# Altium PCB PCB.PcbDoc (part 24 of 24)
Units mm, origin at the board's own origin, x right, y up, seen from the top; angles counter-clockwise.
Board outline 100 x 160 mm, 10 copper layers (TOP_L1, L2, L3, L4, L5, L6, L7, L8, L9, BOTTOM_L10), stack 1.946 mm thick; 1358 components, 1149 nets, 6777 pads, 10914 vias.
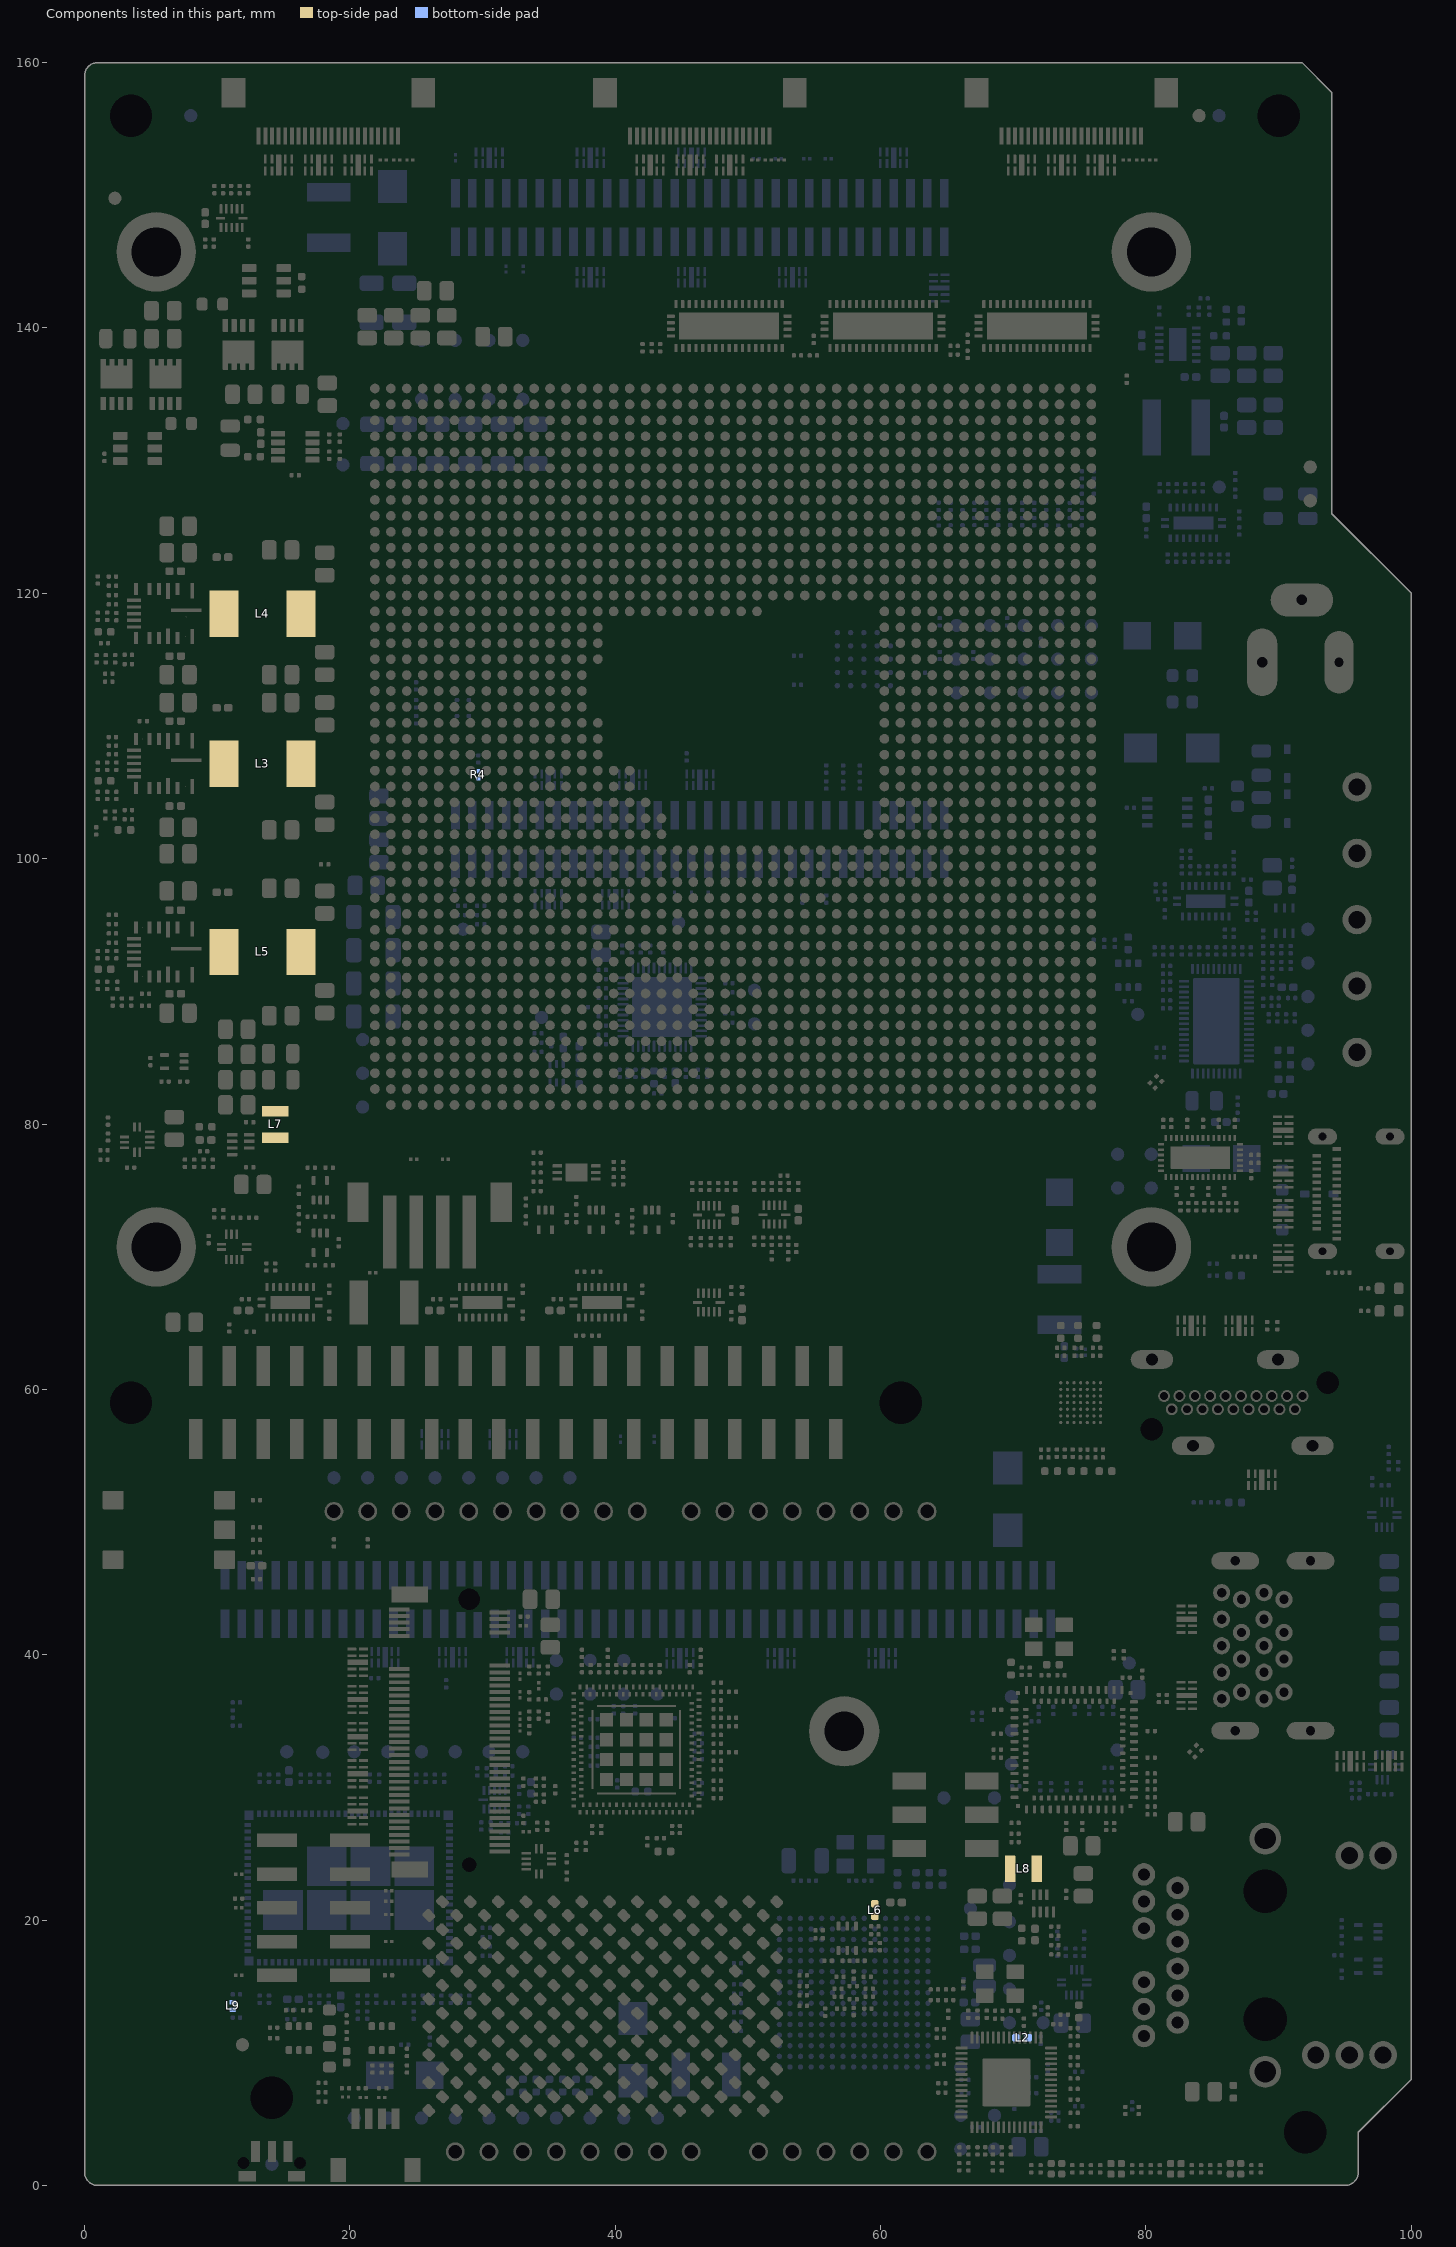
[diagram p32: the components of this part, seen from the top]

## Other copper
TOP_L1:
  pour cut-out: 81.4,79.1 78.2,82.3 69.2,82.3 69.2,80.6 69.8,80 70.338,80 71.838,78.5 77.3,78.5 78.3,77.5 81.4,77.5
  region net +5V: 19.369,89.511 19.369,96.421 14.48,96.421 14.48,98.496 13.37,98.496 13.37,87.431 14.48,87.431 14.48,89.511 17.84,89.511
  region net +5V: 10.14,70.178 10.14,69.008 8.755,69.008 8.755,70.178
  region net PA_VBUS: 2.333,137.7 2.333,140.319 3.899,140.319 3.899,141.893 3.221,142.572 0.808,142.572 0.808,135.438 3.595,135.438 3.595,137.7
  region net NetQ1_S: 11.066,139.698 12.973,139.698 13.104,139.829 13.104,140.672 13.347,140.914 14.766,140.914 14.766,139.698 16.495,139.698 16.495,141.822 11.066,141.822 11.066,140.463
  region net NetQ5_S: 6.635,134.802 4.619,134.802 4.446,134.629 4.446,133.922 4.111,133.586 2.935,133.586 2.935,134.802 1.206,134.802 1.206,132.571 5.67,132.571 5.837,132.571 5.837,133.689 6.635,133.689 6.635,134.037
  region net +3V3: 77.543,26.336 77.543,22.6 73.3,22.6 72.435,22.6 72.435,24.582 75.3,24.582 75.3,26.336
  region net +3V3: 30.7,133.865 26.2,133.865 26.2,136.034 24.85,136.034 24.85,138.365 30.7,138.365
  region net +3V3: 20.55,139.8 20.55,136.95 30.7,136.95 30.7,139.8
  region net +3V3: 19.369,115.01 19.369,121.92 14.48,121.92 14.48,123.795 13.37,123.795 13.37,111.765 14.48,111.765 14.48,115.01 17.84,115.01
  region net +3V3: 19.369,103.71 19.369,110.62 14.48,110.62 14.48,112.495 13.37,112.495 13.37,101.43 14.48,101.43 14.48,103.71 17.84,103.71
  region net +3V3: 23.625,99.036 23.625,103.014 23.075,103.565 21.12,103.565 21.12,110.62 19.1,110.62 19.1,100.765 19.1,99.036
  region net +3V3: 2.982,80.569 5.4,80.569 5.4,82.341 2.982,82.341
  region net +3V3: 34.142,23.118 34.142,22.915 34.541,22.915 34.541,22.423 33.77,22.423 33.612,22.581 33.026,22.581 33.026,23.395 33.789,23.395 33.789,23.118
  pour cut-out: 90.8,88.4 90.8,84 88.5,81.7 85,81.7 78.3,88.4 78.3,100.9 78.9,101.7 78.9,117.3 77.2,119 77.2,127 79.1,128.9 81.8,128.9 83.2,130.3 87,130.3 88.2,129.1 88.2,123.8 85.7,121.3 85.7,90.9 88.1,88.5
  region net PA_VBUS: 95.135,73.354 97.635,73.354 97.635,76.063 95.135,76.063
  region net 7V-24V: 16.9,139.063 16.9,143.358 19.5,143.358 19.5,136.828 14.106,136.828 14.106,139.063 14.405,139.063
  pour cut-out: 86.754,80.471 86.754,83.746 82.5,88 81.6,88 78,91.6 74.98,91.6 74.98,81.6 78.65,81.6 80.85,79.4 86.8,79.4
  region net SOM_VREG_MDPX3_1P8: 76.978,130.488 78.615,130.488 78.615,129.787 77.672,128.844 76.978,128.844
  pour cut-out: 0,46 0,0 10.2,0 10.2,38.781 8.392,40.589 8.392,46
  region net NetC76_1: 2.455,88.188 6.723,88.214 6.723,86.514 2.455,86.514
  region net NetC256_2: 11.709,133.401 11.709,135.699 12.795,136.785 12.795,139.063 8.2,139.063 8.2,137.7 4.906,137.7 4.906,135.438 7.696,135.438 8.4,134.734 8.4,133.8 8.941,133.259 10.089,133.259 10.239,133.109 10.239,132.431 11.709,132.431
  region net NetC96_2: 7.594,93.341 8.837,93.341 9.4,93.904 9.4,94.716 11.6,94.716 11.6,91.216 9.4,91.216 9.4,92.066 8.875,92.591 7.809,92.591
  region net NetC86_2: 7.594,118.84 8.837,118.84 9.4,119.403 9.4,120.215 11.6,120.215 11.6,116.715 9.4,116.715 9.4,117.565 8.875,118.09 7.809,118.09
  region net NetC75_2: 7.594,107.54 8.837,107.54 9.4,108.103 9.4,108.915 11.6,108.915 11.6,105.415 9.4,105.415 9.4,106.265 8.875,106.79 7.809,106.79
  region net GND: 77.341,35.599 71.841,35.599 71.841,30.099 76.941,30.099 77.341,30.499
  region net GND: 7.475,120.765 7.775,120.765 7.775,120.265 8.25,120.265 8.25,120.065 8.8,120.065 8.8,119.565 7.475,119.565
  region net GND: 7.475,116.165 7.775,116.165 7.775,116.665 8.25,116.665 8.25,116.865 8.8,116.865 8.8,117.365 7.475,117.365
  region net GND: 7.475,109.465 7.775,109.465 7.775,108.965 8.25,108.965 8.25,108.765 8.8,108.765 8.8,108.265 7.475,108.265
  region net GND: 7.475,104.865 7.775,104.865 7.775,105.365 8.25,105.365 8.25,105.565 8.8,105.565 8.8,106.065 7.475,106.065
  region net GND: 7.475,95.266 7.775,95.266 7.775,94.766 8.25,94.766 8.25,94.566 8.8,94.566 8.8,94.066 7.475,94.066
  region net GND: 7.475,90.666 7.775,90.666 7.775,91.166 8.25,91.166 8.25,91.366 8.8,91.366 8.8,91.866 7.475,91.866
  region net "1V05_PG (PULLUP 1V8)_1": 72.906,22.309 72.906,21.409 73.032,21.409 73.156,21.533 73.156,22.309
  region net NetR337_2: 2.665,79.319 3.365,79.319 3.365,79.423 3.269,79.519 2.665,79.519
  region net NetR217_2: 3.2,91.166 4.25,91.166 4.25,90.666 4.525,90.666 4.525,91.394 4.353,91.566 3.2,91.566
  region net NetC114_2: 3.2,94.766 4.25,94.766 4.25,95.266 4.525,95.266 4.525,94.366 3.2,94.366
  region net NetC96_2: 8.8,92.591 8.8,92.841 8.3,92.841 8.3,93.341 6.5,93.341 6.5,92.841 6.5,92.591
  region net NetC144_2: 3.2,108.965 4.25,108.965 4.25,109.465 4.525,109.465 4.525,108.565 3.2,108.565
  region net "3V3_PG (PULLUP 3V3)_1": 3.2,105.365 4.25,105.365 4.25,104.865 4.525,104.865 4.525,105.593 4.353,105.765 3.2,105.765
  region net NetC75_2: 8.8,106.79 8.8,107.04 8.3,107.04 8.3,107.54 6.5,107.54 6.5,107.04 6.5,106.79
  region net NetR123_2: 3.2,116.665 4.25,116.665 4.25,116.165 4.525,116.165 4.525,116.893 4.353,117.065 3.2,117.065
  region net NetC145_2: 3.2,120.265 4.25,120.265 4.25,120.765 4.525,120.765 4.525,119.865 3.2,119.865
  region net NetC86_2: 8.8,118.09 8.8,118.34 8.3,118.34 8.3,118.84 6.5,118.84 6.5,118.34 6.5,118.09
  region net NetR150_2: 12.818,77.816 11.918,77.816 11.918,77.69 12.042,77.566 12.818,77.566
  region net MD_GPIO_51_1: 35.541,23.924 34.841,23.924 34.841,23.82 34.937,23.724 35.541,23.724
  region net NetR336_2: 11.768,72.036 11.768,71.336 11.872,71.336 11.968,71.432 11.968,72.036
L5:
  pour cut-out: 0,46 0,0 10.2,0 10.2,38.781 8.392,40.589 8.392,46
L6:
  pour cut-out: 0,46 0,0 10.2,0 10.2,38.781 8.392,40.589 8.392,46
L2:
  pour cut-out: 0,46 0,0 10.2,0 10.2,38.781 8.392,40.589 8.392,46
L3:
  pour cut-out: 0,46 0,0 10.2,0 10.2,38.781 8.392,40.589 8.392,46
L4:
  pour cut-out: 0,46 0,0 10.2,0 10.2,38.781 8.392,40.589 8.392,46
L7:
  pour cut-out: 0,46 0,0 10.2,0 10.2,38.781 8.392,40.589 8.392,46
L8:
  pour cut-out: 0,46 0,0 10.2,0 10.2,38.781 8.392,40.589 8.392,46
L9:
  pour cut-out: 0,46 0,0 10.2,0 10.2,38.781 8.392,40.589 8.392,46
BOTTOM_L10:
  rectangle net NetC84_2: 84.675,82.701 85.953,83.246
  region net GND: 8,1.651 8,0.651 0.5,0.651 0.5,20.901 10.5,20.901 10.5,19.901 1.5,19.901 1.5,13.151 6.75,13.151 6.75,16.151 5.25,16.151 5.25,17.151 8.75,17.151 8.75,13.151 10.01,13.151 10.01,12.151 5.75,12.151 5.75,6.151 2.5,6.151 2.5,7.151 4,7.151 4,12.151 1.5,12.151 1.5,1.651
  region net +3V3: 21.15,110.7 17.943,110.7 14.85,110.7 14.85,103.2 19.35,103.2 19.35,99 21.15,99
  region net NetLOVE_X: 1461 vertices and 0 holes, not listed, extent 68.468,21.376 70.924,23.748
  region net ANT1_PI_29: 4,39.651 4,35.901 10.01,35.901 10.01,36.901 5,36.901 5,39.651
  pour cut-out: 10.136,12.698 10.136,12.605 11.167,12.605 11.167,12.698
  region net ANT0_PI_29: 10.01,13.151 10.463,12.698 11.201,12.698 11.201,12.605 10.464,12.605 10.01,12.151
  region net ANT1_PI_29: 10.01,36.901 10.463,36.448 11.201,36.448 11.201,36.355 10.464,36.355 10.01,35.901
  pour cut-out: 0,46 0,0 10.2,0 10.2,38.781 8.392,40.589 8.392,46
  region net PA_VBUS: 97.603,73.325 95.024,73.325 95.024,76.181 97.603,76.181
  pour cut-out: 10.153,36.571 10.153,36.234 11.185,36.234 11.185,36.571
  region net DVDD18: 73.815,13.833 73.815,13.454 75.985,13.454 75.985,13.833
  region net GND: 80.803,102.652 80.803,104.753 82.403,104.753 82.403,102.253 81.202,102.253
  region net GND: 91.133,95.674 91.133,94.973 89.733,94.973 89.733,95.516 89.89,95.674
  region net GND: 16.45,25.56 16.45,22.56 13.45,22.56 13.45,25.06 13.95,25.56
  region net NetR154_2: 97.471,51.846 97.471,51.146 97.367,51.146 97.271,51.242 97.271,51.846
  region net NetR182_2: 98.515,30.235 98.515,30.935 98.619,30.935 98.715,30.838 98.715,30.235
  region net NetC36_2: 74.081,16.609 74.081,15.909 73.977,15.909 73.881,16.005 73.881,16.609
  text ".Version" at 87.016,3.5 h1

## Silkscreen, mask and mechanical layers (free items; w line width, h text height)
Board:
  the board outline again, w0.2
TH_CLEARANCES:
  circle w0.05: c97.727,79.628 r3
  circle w0.05: c95.9,105.4 r3
  circle w0.05: c95.9,100.4 r3
  circle w0.05: c95.9,95.4 r3
  circle w0.05: c95.9,90.4 r3
  circle w0.05: c95.9,85.4 r3
  circle w0.05: c92.361,79.474 r3
  circle w0.05: c78.857,62.364 r3
  circle w0.05: c85.054,47.465 r3
  circle w0.05: c95.334,9.83 r3.711
  circle w0.05: c92.794,9.83 r3.711
  circle w0.05: c88.984,8.56 r3.711
  circle w0.05: c94.142,34.005 r3
  circle w0.05: c97.874,24.87 r3.711
  circle w0.05: c95.334,24.87 r3.711
  circle w0.05: c88.984,26.14 r3.711
  circle w0.05: c79.844,11.26 r3.711
  circle w0.05: c79.844,13.29 r3.711
  circle w0.05: c79.844,15.32 r3.711
  circle w0.05: c79.844,19.38 r3.711
  circle w0.05: c79.844,21.41 r3.711
  circle w0.05: c79.844,23.44 r3.711
  circle w0.05: c53.34,2.54 r3.711
  circle w0.05: c27.94,2.54 r3.711
  circle w0.05: c30.48,2.54 r3.711
  circle w0.05: c33.02,2.54 r3.711
  circle w0.05: c35.56,2.54 r3.711
  circle w0.05: c38.1,2.54 r3.711
  circle w0.05: c40.64,2.54 r3.711
  circle w0.05: c58.42,50.8 r3.711
  circle w0.05: c55.88,50.8 r3.711
  circle w0.05: c53.34,50.8 r3.711
  circle w0.05: c50.8,50.8 r3.711
  circle w0.05: c18.796,50.8 r3.711
  circle w0.05: c21.336,50.8 r3.711
  circle w0.05: c23.876,50.8 r3.711
  circle w0.05: c39.116,50.8 r3.711
  circle w0.05: c45.72,50.8 r3.711
  circle w0.05: c41.656,50.8 r3.711
  circle w0.05: c28.956,50.8 r3.711
  circle w0.05: c34.036,50.8 r3.711
  circle w0.05: c63.5,2.54 r3.711
  circle w0.05: c60.96,2.54 r3.711
  circle w0.05: c58.42,2.54 r3.711
  circle w0.05: c55.88,2.54 r3.711
  circle w0.05: c43.18,2.54 r3.711
  circle w0.05: c45.72,2.54 r3.711
  circle w0.05: c50.8,2.54 r3.711
  circle w0.05: c36.576,50.8 r3.711
  circle w0.05: c26.416,50.8 r3.711
  circle w0.05: c31.496,50.8 r3.711
  circle w0.05: c63.5,50.8 r3.711
  circle w0.05: c93.972,47.575 r3
  circle w0.05: c94.04,55.294 r3
Drill Drawing:
  drawing of 151 lines, arcs and shapes, not listed
  text "Symbol" at 121.976,164.215 h1.83
  text "Count" at 134.826,164.215 h1.83
  text "Hole Size" at 150.062,164.215 h1.83
  text "Plated" at 179.263,164.215 h1.83
  text "Hole Type" at 192.112,164.215 h1.83
  text "Drill Layer Pair" at 210.751,164.215 h1.83
  text "Via/Pad" at 241.476,164.215 h1.83
  text "Pad Shape" at 256.458,164.215 h1.83
  text "Template" at 275.401,164.215 h1.83
  text "Description" at 329.487,164.215 h1.83
  text "Hole Tolerance (+)" at 351.172,164.215 h1.83
  text "Hole Tolerance (-)" at 385.046,164.215 h1.83
  text "Hole Length" at 418.92,164.215 h1.83
  text "Routed Path Length" at 448.121,164.215 h1.83
  text "1" at 134.826,160.405 h1.52
  text "27.56mil (0.700mm)" at 150.062,160.405 h1.52
  text "PTH" at 179.263,160.405 h1.52
  text "Slot" at 192.112,160.405 h1.52
  text "TOP_L1 - BOTTOM_L10" at 210.751,160.405 h1.52
  text "Pad" at 241.476,160.405 h1.52
  text "Rounded" at 256.458,160.405 h1.52
  text "r470_220h70_320r110m0mx0" at 275.401,160.405 h1.52
  text "125.98mil (3.200mm)" at 418.92,160.405 h1.52
  text "98.43mil (2.500mm)" at 448.121,160.405 h1.52
  text "1" at 134.826,156.595 h1.52
  text "31.50mil (0.800mm)" at 150.062,156.595 h1.52
  text "PTH" at 179.263,156.595 h1.52
  text "Slot" at 192.112,156.595 h1.52
  text "TOP_L1 - BOTTOM_L10" at 210.751,156.595 h1.52
  text "Pad" at 241.476,156.595 h1.52
  text "Rounded" at 256.458,156.595 h1.52
  text "r470_250h80_320r125m0mx0" at 275.401,156.595 h1.52
  text "125.98mil (3.200mm)" at 418.92,156.595 h1.52
  text "94.49mil (2.400mm)" at 448.121,156.595 h1.52
  text "1" at 134.826,152.785 h1.52
  text "31.50mil (0.800mm)" at 150.062,152.785 h1.52
  text "PTH" at 179.263,152.785 h1.52
  text "Slot" at 192.112,152.785 h1.52
  text "TOP_L1 - BOTTOM_L10" at 210.751,152.785 h1.52
  text "Pad" at 241.476,152.785 h1.52
  text "Rounded" at 256.458,152.785 h1.52
  text "r510_230h80_360r115m0mx0" at 275.401,152.785 h1.52
  text "141.73mil (3.600mm)" at 418.92,152.785 h1.52
  text "110.24mil (2.800mm)" at 448.121,152.785 h1.52
  text "1" at 134.826,148.975 h1.52
  text "43.31mil (1.100mm)" at 150.062,148.975 h1.52
  text "NPTH" at 179.263,148.975 h1.52
  text "Round" at 192.112,148.975 h1.52
  text "TOP_L1 - BOTTOM_L10" at 210.751,148.975 h1.52
  text "Pad" at 241.476,148.975 h1.52
  text "Rounded" at 256.458,148.975 h1.52
  text "c0hn110m0mx0" at 275.401,148.975 h1.52
  text "-" at 418.92,148.975 h1.52
  text "-" at 448.121,148.975 h1.52
  text "1" at 134.826,145.165 h1.52
  text "62.99mil (1.600mm)" at 150.062,145.165 h1.52
  text "NPTH" at 179.263,145.165 h1.52
  text "Round" at 192.112,145.165 h1.52
  text "TOP_L1 - BOTTOM_L10" at 210.751,145.165 h1.52
  text "Pad" at 241.476,145.165 h1.52
  text "Rounded" at 256.458,145.165 h1.52
  text "c0hn160m0mx0" at 275.401,145.165 h1.52
  text "-" at 418.92,145.165 h1.52
  text "-" at 448.121,145.165 h1.52
  text "1" at 134.826,141.355 h1.52
  text "118.11mil (3.000mm)" at 150.062,141.355 h1.52
  text "PTH" at 179.263,141.355 h1.52
  text "Round" at 192.112,141.355 h1.52
  text "TOP_L1 - BOTTOM_L10" at 210.751,141.355 h1.52
  text "Pad" at 241.476,141.355 h1.52
  text "Rounded" at 256.458,141.355 h1.52
  text "c530h300m550" at 275.401,141.355 h1.52
  text "-" at 418.92,141.355 h1.52
  text "-" at 448.121,141.355 h1.52
  text "2" at 134.826,137.545 h1.52
  text "35.43mil (0.900mm)" at 150.062,137.545 h1.52
  text "NPTH" at 179.263,137.545 h1.52
  text "Round" at 192.112,137.545 h1.52
  text "TOP_L1 - BOTTOM_L10" at 210.751,137.545 h1.52
  text "Pad" at 241.476,137.545 h1.52
  text "Rounded" at 256.458,137.545 h1.52
  text "c50hn90m0mx0" at 275.401,137.545 h1.52
  text "-" at 418.92,137.545 h1.52
  text "-" at 448.121,137.545 h1.52
  text "2" at 134.826,133.735 h1.52
  text "62.99mil (1.600mm)" at 150.062,133.735 h1.52
  text "PTH" at 179.263,133.735 h1.52
  text "Round" at 192.112,133.735 h1.52
  text "TOP_L1 - BOTTOM_L10" at 210.751,133.735 h1.52
  text "Pad" at 241.476,133.735 h1.52
  text "Rounded" at 256.458,133.735 h1.52
  text "c240h160m260(Tol20-0)" at 275.401,133.735 h1.52
  text "7.87mil (0.200mm)" at 351.172,133.735 h1.52
  text "0.00mil (0.000mm)" at 385.046,133.735 h1.52
  text "-" at 418.92,133.735 h1.52
  text "-" at 448.121,133.735 h1.52
  text "2" at 134.826,129.925 h1.52
  text "66.93mil (1.700mm)" at 150.062,129.925 h1.52
  text "NPTH" at 179.263,129.925 h1.52
  text "Round" at 192.112,129.925 h1.52
  text "TOP_L1 - BOTTOM_L10" at 210.751,129.925 h1.52
  text "Pad" at 241.476,129.925 h1.52
  text "Rounded" at 256.458,129.925 h1.52
  text "c135hn170m145(Tol20-0)" at 275.401,129.925 h1.52
  text "7.87mil (0.200mm)" at 351.172,129.925 h1.52
  text "0.00mil (0.000mm)" at 385.046,129.925 h1.52
  text "-" at 418.92,129.925 h1.52
  text "-" at 448.121,129.925 h1.52
  text "G" at 121.238,129.671 h1.69
  text "2" at 134.826,126.115 h1.52
  text "127.95mil (3.250mm)" at 150.062,126.115 h1.52
  text "NPTH" at 179.263,126.115 h1.52
  text "Round" at 192.112,126.115 h1.52
  text "TOP_L1 - BOTTOM_L10" at 210.751,126.115 h1.52
  text "Pad" at 241.476,126.115 h1.52
  text "Rounded" at 256.458,126.115 h1.52
  text "c200hn325m220(Tol20-0)" at 275.401,126.115 h1.52
  text "7.87mil (0.200mm)" at 351.172,126.115 h1.52
  text "0.00mil (0.000mm)" at 385.046,126.115 h1.52
  text "-" at 418.92,126.115 h1.52
  text "-" at 448.121,126.115 h1.52
  text "B" at 121.238,125.861 h1.69
  text "4" at 134.826,122.305 h1.52
  text "23.62mil (0.600mm)" at 150.062,122.305 h1.52
  text "PTH" at 179.263,122.305 h1.52
  text "Slot" at 192.112,122.305 h1.52
  text "TOP_L1 - BOTTOM_L10" at 210.751,122.305 h1.52
  text "Pad" at 241.476,122.305 h1.52
  text "Rounded" at 256.458,122.305 h1.52
  text "r220_120h60_160r60m230_130" at 275.401,122.305 h1.52
  text "62.99mil (1.600mm)" at 418.92,122.305 h1.52
  text "39.37mil (1.000mm)" at 448.121,122.305 h1.52
  text "A" at 121.238,122.051 h1.69
  text "4" at 134.826,118.495 h1.52
  text "27.56mil (0.700mm)" at 150.062,118.495 h1.52
  text "PTH" at 179.263,118.495 h1.52
  text "Slot" at 192.112,118.495 h1.52
  text "TOP_L1 - BOTTOM_L10" at 210.751,118.495 h1.52
  text "Pad" at 241.476,118.495 h1.52
  text "Rounded" at 256.458,118.495 h1.52
  text "r360_130h70_300r65m380_150" at 275.401,118.495 h1.52
  text "118.11mil (3.000mm)" at 418.92,118.495 h1.52
  text "90.55mil (2.300mm)" at 448.121,118.495 h1.52
  text "4" at 134.826,114.685 h1.52
  text "35.43mil (0.900mm)" at 150.062,114.685 h1.52
  text "PTH" at 179.263,114.685 h1.52
  text "Slot" at 192.112,114.685 h1.52
  text "TOP_L1 - BOTTOM_L10" at 210.751,114.685 h1.52
  text "Pad" at 241.476,114.685 h1.52
  text "Rounded" at 256.458,114.685 h1.52
  text "r320_140h90_270r70m330_150(Tol20-0)" at 275.401,114.685 h1.52
  text "7.87mil (0.200mm)" at 351.172,114.685 h1.52
  text "0.00mil (0.000mm)" at 385.046,114.685 h1.52
  text "106.30mil (2.700mm)" at 418.92,114.685 h1.52
  text "70.87mil (1.800mm)" at 448.121,114.685 h1.52
  text "H" at 121.238,114.431 h1.69
  text "4" at 134.826,110.875 h1.52
  text "145.67mil (3.700mm)" at 150.062,110.875 h1.52
  text "PTH" at 179.263,110.875 h1.52
  text "Round" at 192.112,110.875 h1.52
  text "TOP_L1 - BOTTOM_L10" at 210.751,110.875 h1.52
  text "Pad" at 241.476,110.875 h1.52
  text "Rounded" at 256.458,110.875 h1.52
  text "c600h370m620" at 275.401,110.875 h1.52
  text "-" at 418.92,110.875 h1.52
  text "-" at 448.121,110.875 h1.52
  text "5" at 134.826,107.065 h1.52
  text "50.00mil (1.270mm)" at 150.062,107.065 h1.52
  text "PTH" at 179.263,107.065 h1.52
  text "Round" at 192.112,107.065 h1.52
  text "TOP_L1 - BOTTOM_L10" at 210.751,107.065 h1.52
  text "Pad" at 241.476,107.065 h1.52
  text "Rounded" at 256.458,107.065 h1.52
  text "c210h127m230(Tol20-0)" at 275.401,107.065 h1.52
  text "7.87mil (0.200mm)" at 351.172,107.065 h1.52
  text "0.00mil (0.000mm)" at 385.046,107.065 h1.52
  text "-" at 418.92,107.065 h1.52
  text "-" at 448.121,107.065 h1.52
  text "D" at 121.238,106.811 h1.69
  text "5" at 134.826,103.255 h1.52
  text "51.18mil (1.300mm)" at 150.062,103.255 h1.52
  text "PTH" at 179.263,103.255 h1.52
  text "Round" at 192.112,103.255 h1.52
  text "TOP_L1 - BOTTOM_L10" at 210.751,103.255 h1.52
  text "Pad" at 241.476,103.255 h1.52
  text "Rounded" at 256.458,103.255 h1.52
  text "c220h130m230(Tol30-0)" at 275.401,103.255 h1.52
  text "11.81mil (0.300mm)" at 351.172,103.255 h1.52
  text "0.00mil (0.000mm)" at 385.046,103.255 h1.52
  text "-" at 418.92,103.255 h1.52
  text "-" at 448.121,103.255 h1.52
  text "6" at 134.826,99.445 h1.52
  text "125.98mil (3.200mm)" at 150.062,99.445 h1.52
  text "NPTH" at 179.263,99.445 h1.52
  text "Round" at 192.112,99.445 h1.52
  text "TOP_L1 - BOTTOM_L10" at 210.751,99.445 h1.52
  text "Pad" at 241.476,99.445 h1.52
  text "Rounded" at 256.458,99.445 h1.52
  text "c300hn320m560p0(Tol20-0)" at 275.401,99.445 h1.52
  text "7.87mil (0.200mm)" at 351.172,99.445 h1.52
  text "0.00mil (0.000mm)" at 385.046,99.445 h1.52
  text "-" at 418.92,99.445 h1.52
  text "-" at 448.121,99.445 h1.52
  text "12" at 134.826,95.635 h1.52
  text "35.04mil (0.890mm)" at 150.062,95.635 h1.52
  text "PTH" at 179.263,95.635 h1.52
  text "Round" at 192.112,95.635 h1.52
  text "TOP_L1 - BOTTOM_L10" at 210.751,95.635 h1.52
  text "Pad" at 241.476,95.635 h1.52
  text "Rounded" at 256.458,95.635 h1.52
  text "c170h89m190(Tol20-0)" at 275.401,95.635 h1.52
  text "7.87mil (0.200mm)" at 351.172,95.635 h1.52
  text "0.00mil (0.000mm)" at 385.046,95.635 h1.52
  text "-" at 418.92,95.635 h1.52
  text "-" at 448.121,95.635 h1.52
  text "C" at 121.238,95.381 h1.69
  text "18" at 134.826,91.825 h1.52
  text "27.56mil (0.700mm)" at 150.062,91.825 h1.52
  text "PTH" at 179.263,91.825 h1.52
  text "Round" at 192.112,91.825 h1.52
  text "TOP_L1 - BOTTOM_L10" at 210.751,91.825 h1.52
  text "Pad" at 241.476,91.825 h1.52
  text "Rounded" at 256.458,91.825 h1.52
  text "c130h70m140" at 275.401,91.825 h1.52
  text "-" at 418.92,91.825 h1.52
  text "-" at 448.121,91.825 h1.52
  text "M" at 121.238,91.571 h1.69
  text "19" at 134.826,88.015 h1.52
  text "23.62mil (0.600mm)" at 150.062,88.015 h1.52
  text "PTH" at 179.263,88.015 h1.52
  text "Round" at 192.112,88.015 h1.52
  text "TOP_L1 - BOTTOM_L10" at 210.751,88.015 h1.52
  text "Pad" at 241.476,88.015 h1.52
  text "Rounded" at 256.458,88.015 h1.52
  text "c90h60m100(Tol20-0)" at 275.401,88.015 h1.52
  text "7.87mil (0.200mm)" at 351.172,88.015 h1.52
  text "0.00mil (0.000mm)" at 385.046,88.015 h1.52
  text "-" at 418.92,88.015 h1.52
  text "-" at 448.121,88.015 h1.52
  text "F" at 121.238,87.761 h1.69
  text "32" at 134.826,84.205 h1.52
  text "40.16mil (1.020mm)" at 150.062,84.205 h1.52
  text "PTH" at 179.263,84.205 h1.52
  text "Round" at 192.112,84.205 h1.52
  text "TOP_L1 - BOTTOM_L10" at 210.751,84.205 h1.52
  text "Pad" at 241.476,84.205 h1.52
  text "Rounded" at 256.458,84.205 h1.52
  text "c142h102" at 275.401,84.205 h1.52
  text "-" at 418.92,84.205 h1.52
  text "-" at 448.121,84.205 h1.52
  text "600" at 134.826,80.395 h1.52
  text "11.81mil (0.300mm)" at 150.062,80.395 h1.52
  text "PTH" at 179.263,80.395 h1.52
  text "Round" at 192.112,80.395 h1.52
  text "TOP_L1 - BOTTOM_L10" at 210.751,80.395 h1.52
  text "Via" at 241.476,80.395 h1.52
  text "Rounded" at 256.458,80.395 h1.52
  text "(Mixed)" at 275.401,80.395 h1.52
  text "-" at 418.92,80.395 h1.52
  text "-" at 448.121,80.395 h1.52
  text "K" at 121.238,80.141 h1.69
  text "727 Total" at 134.826,76.585 h1.52
  text "Slot definitions :" at 121.976,72.903 h1.52
  text "Routed Path Length" at 148.207,72.903 h1.52
  text "= Calculated from tool start centre position to tool end centre position." at 176.215,72.903 h1.52
  text "Hole Length" at 148.207,70.363 h1.52
  text "= Routed Path Length + Tool Size = Slot length as defined in the PCB layout" at 165.804,70.363 h1.52
2D UNO R4:
  drawing of 639 lines, arcs and shapes, not listed
  text "FIXING HOLE DIAMETER 1.6mm" at 13.865,49.68 h0.3
  text "PUSHBUTTON" at 3.341,49.14 h0.6
  text "JDIGITAL" at 39.041,48.64 h0.6
  text "RGB" at 61.94,47.14 h0.6
  text "RGB" at 61.94,45.54 h0.6
  text "JCTL" at 20.092,44.973 h0.6
  text "RGB" at 61.94,43.94 h0.6
  text "RGB" at 61.94,42.34 h0.6
  text "PWR LED" at 59.941,38.64 h0.6
  text "USBC" at 0.94,36.94 h0.6
  text "FIXING HOLE DIAMETER 1.6mm" at 64.665,34.44 h0.3
  text "JSPI" at 63.94,23.24 h0.6
  text "13x8 LED MATRIX" at 41.949,22.305 h0.6
  text "QWIIC" at 64.44,18.04 h0.6
  text "FIXING HOLE DIAMETER 1.6mm" at 64.665,6.5 h0.3
  text "JBAT" at 19.306,4.224 h0.6
  text "JANALOG" at 45.441,4.14 h0.6
  text "FIXING HOLE DIAMETER 1.6mm" at 12.595,1.42 h0.3
2D RASPBERRY HAT:
  circle w0.05: c61.5,10.03 r3
  circle w0.05: c3.5,10.03 r3
  circle w0.05: c61.5,59.029 r3
  circle w0.05: c3.5,59.029 r3
  lines w0.2: 6.5,6.249 62,6.249 ccw(c62,9.249) 65,9.249 65,59.81 ; 6.5,62.81 3,62.81 ccw(c3,59.81) 0,59.81 0,9.249 ccw(c3,9.249) 3,6.249 6.651,6.249 ; 29,59 32.5,59 ; 32.5,55.5 32.5,59 ; 32.5,62.5 32.5,59 ; 32.5,59 36,59 ; 58.5,62.81 62,62.81 cw(c62,59.81) 65,59.81
2D UNO Q CARRIER:
  lines w0.05: 44.618,101.453 46.374,101.453 ; 44.618,148.316 46.374,148.316 ; 46.374,99.697 46.374,101.453 ; 46.374,103.209 46.374,101.453 ; 46.374,146.56 46.374,148.316 ; 46.374,150.072 46.374,148.316 ; 48.13,101.453 46.374,101.453 ; 48.13,148.316 46.374,148.316 ; 63.033,103.296 64.789,103.296 ; 63.033,150.159 64.789,150.159 ; 64.789,101.54 64.789,103.296 ; 64.789,105.052 64.789,103.296 ; 64.789,148.403 64.789,150.159 ; 64.789,151.915 64.789,150.159 ; 66.545,103.296 64.789,103.296 ; 66.545,150.159 64.789,150.159 ; 19.704,94.96 ccw(c20.704,94.96) 20.704,93.96 ; 19.704,94.96 ccw(c19.704,94.96) 19.704,94.96 ; 19.704,94.96 19.704,159 ; 19.704,159 ccw(c19.704,159) 19.704,159 ; 19.704,159 cw(c20.704,159) 20.704,160 72.044,160 cw(c72.044,159) 73.044,159 73.044,95.484 ; 20.704,93.96 22.244,93.96 ; 20.704,93.96 22.244,93.96 ; 22.244,93.96 24.784,91.42 ; 22.244,93.96 24.784,91.42 ; 24.784,91.42 57.55,91.42 ; 24.784,91.42 57.55,91.42 ; 57.55,91.42 60.09,93.96 ; 57.55,91.42 60.09,93.96 ; 60.09,93.96 71.52,93.96 ; 60.09,93.96 71.52,93.96 ; 71.52,93.96 73.044,95.484 ; 71.52,93.96 73.044,95.484 ; 73.044,95.484 ccw(c73.044,95.484) 73.044,95.484
2D HEATSINK:
  lines w0.05: 13.351,66.536 13.351,80.536 71.851,80.536 71.851,66.536 ; 32.601,109.036 42.601,109.036 ; 42.601,99.036 42.601,109.036 ; 42.601,119.036 42.601,109.036 ; 52.601,109.036 42.601,109.036 ; 84.601,78.536 70.601,78.536 70.601,139.536 84.601,139.536 ; 0.601,66.536 0.601,151.536 84.601,151.536 84.601,66.536 0.601,66.536 ; 57.701,130.336 57.701,133.436 75.301,133.436 75.301,130.336 57.701,130.336
ANTENNA_SINGLE:
  lines w0.013: -30.922,-64.207 ccw(c-29.921,-64.206) -29.922,-65.207 ; -30.922,93.793 cw(c-29.921,93.793) -29.922,94.793 ; 64.078,-65.207 ccw(c64.078,-64.206) 65.078,-64.207 ; 0,9.2 10.2,9.2 ; 0,9.2 0,39.25 ; 0,9.2 10.2,9.2 ; 0,39.25 10.2,39.25 ; 0,39.25 10.2,39.25 ; 10.2,9.2 10.2,39.25 ; 10.2,9.2 10.2,39.25 ; 0.2,17.25 0.2,37.25 5.7,37.25 5.7,36.25 4.2,36.25 4.2,28.25 10.2,28.25 10.2,27.25 4.2,27.25 4.2,18.25 8.2,18.25 8.2,23.25 10.2,23.25 10.2,22.25 9.2,22.25 9.2,17.25 0.2,17.25
ANTENNA_DOUBLE_20260203:
  lines w0.013: 0,46.001 0,4.001 0,0 10.2,0 10.2,21.901 ; 0,46.001 10.2,46.001 ; 0,46.001 10.2,46.001 ; 0,46.001 0,59.001 ; 0,59.001 1.9,59.001 ; 0,59.001 1.9,59.001 ; 0,59.001 0,159.001 cw(c1,159.001) 1,160.001 91.749,160.001 94,157.75 94,128.001 100,122.001 100,10.001 96,6.001 96,1.001 cw(c95,1.001) 95,0.001 10.2,0.001 10.2,21.901 ; 0.2,11.901 0.2,43.651 ; 0.2,11.901 3.7,11.901 ; 0.2,11.901 3.7,11.901 ; 0.2,11.901 0.2,43.651 ; 0.2,43.651 3.2,43.651 ; 0.2,43.651 3.2,43.651 ; 1.2,12.901 1.2,21.901 ; 1.2,12.901 6.2,12.901 ; 1.2,12.901 1.2,21.901 ; 1.2,12.901 6.2,12.901 ; 1.2,21.901 10.2,21.901 ; 1.2,21.901 10.2,21.901 ; 1.2,22.901 10.2,22.901 ; 1.2,22.901 1.2,31.651 ; 1.2,22.901 1.2,31.651 ; 1.2,22.901 10.2,22.901 ; 1.2,31.651 6.2,31.651 ; 1.2,31.651 6.2,31.651 ; 1.2,32.651 3.7,32.651 ; 1.2,32.651 1.2,42.651 ; 1.2,32.651 1.2,42.651 ; 1.2,32.651 3.7,32.651 ; 1.2,42.651 3.2,42.651 ; 1.2,42.651 3.2,42.651 ; 1.9,59.001 ccw(c3.5,59.001) 5.1,59.001 ccw(c3.5,59.001) 1.9,59.001 ; 3.2,42.651 3.2,43.651 ; 3.2,42.651 3.2,43.651 ; 3.61,5.597 ccw(c3.5,4.001) 5.1,4.001 ccw(c3.5,4.001) 3.61,5.597 ; 3.61,5.597 3.7,6.901 ; 3.61,5.597 3.7,6.901 ; 3.7,6.901 3.7,11.901 ; 3.7,6.901 5.7,6.901 ; 3.7,6.901 5.7,6.901 ; 3.7,6.901 3.7,11.901 ; 3.7,32.651 3.7,39.901 ; 3.7,32.651 3.7,39.901 ; 3.7,39.901 5.7,39.901 ; 3.7,39.901 5.7,39.901 ; 4.7,27.651 4.7,28.651 ; 4.7,27.651 8.2,27.651 ; 4.7,27.651 8.2,27.651 ; 4.7,27.651 4.7,28.651 ; 4.7,28.651 6.2,28.651 ; 4.7,28.651 6.2,28.651 ; 5.7,6.901 5.7,11.901 ; 5.7,6.901 5.7,11.901 ; 5.7,11.901 9.7,11.901 ; 5.7,11.901 9.7,11.901 ; 5.7,32.651 9.7,32.651 ; 5.7,32.651 5.7,39.901 ; 5.7,32.651 5.7,39.901 ; 5.7,32.651 9.7,32.651 ; 6.2,12.901 6.2,16.901 ; 6.2,12.901 6.2,16.901 ; 6.2,16.901 8.2,16.901 ; 6.2,16.901 8.2,16.901 ; 6.2,28.651 6.2,31.651 ; 6.2,28.651 6.2,31.651 ; 8.2,12.901 9.7,12.901 ; 8.2,12.901 8.2,16.901 ; 8.2,12.901 8.2,16.901 ; 8.2,12.901 9.7,12.901 ; 8.2,27.651 8.2,31.651 ; 8.2,27.651 8.2,31.651 ; 8.2,31.651 9.7,31.651 ; 8.2,31.651 9.7,31.651 ; 9.7,11.901 9.7,12.901 ; 9.7,11.901 9.7,12.901 ; 9.7,31.651 9.7,32.651 ; 9.7,31.651 9.7,32.651 ; 10.2,22.901 10.2,46.001 ; 10.2,22.901 10.2,46.001
  lines w0.05: 49.939,6.505 65.987,6.505 65.987,22.553 49.939,22.553 49.939,6.505
ANTENNA_DOUBLE_20260326:
  lines w0.013: 0,46.001 0,0 10.2,0 10.2,19.901 ; 0,46.001 0,59.001 ; 0,46.001 3.7,46.001 ; 0,46.001 8.523,46.001 ; 0,59.001 0,159.001 cw(c1,159.001) 1,160.001 91.749,160.001 94,157.75 94,128.001 100,122.001 100,10.001 96,6.001 96,1.001 cw(c95,1.001) 95,0.001 10.2,0.001 10.2,19.901 ; 0,59.001 1.9,59.001 ; 0,59.001 1.9,59.001 ; 0.2,0.651 7.7,0.651 ; 0.2,0.651 7.7,0.651 ; 0.2,0.651 0.2,20.901 ; 0.2,0.651 0.2,20.901 ; 0.2,20.901 10.2,20.901 ; 0.2,20.901 10.2,20.901 ; 1.2,1.651 7.7,1.651 ; 1.2,1.651 7.7,1.651 ; 1.2,1.651 1.2,12.151 ; 1.2,1.651 1.2,12.151 ; 1.2,12.151 3.7,12.151 ; 1.2,12.151 3.7,12.151 ; 1.2,13.151 1.2,19.901 ; 1.2,13.151 1.2,19.901 ; 1.2,13.151 6.45,13.151 ; 1.2,13.151 6.45,13.151 ; 1.2,19.901 10.2,19.901 ; 1.2,19.901 10.2,19.901 ; 1.9,59.001 cw(c3.5,59.001) 5.1,59.001 cw(c3.5,59.001) 1.9,59.001 ; 2.2,6.151 5.45,6.151 ; 2.2,6.151 5.45,6.151 ; 2.2,6.151 2.2,7.151 ; 2.2,6.151 2.2,7.151 ; 2.2,7.151 3.7,7.151 ; 2.2,7.151 3.7,7.151 ; 3.7,7.151 3.7,12.151 ; 3.7,7.151 3.7,12.151 ; 3.7,35.901 9.7,35.901 ; 3.7,35.901 3.7,39.651 ; 3.7,35.901 3.7,39.651 ; 3.7,35.901 9.7,35.901 ; 3.7,39.651 4.7,39.651 ; 3.7,39.651 4.7,39.651 ; 3.7,39.651 3.7,46.001 ; 3.7,39.651 3.7,46.001 ; 3.7,46.001 8.523,46.001 ; 4.7,36.901 9.7,36.901 ; 4.7,36.901 9.7,36.901 ; 4.7,36.901 4.7,39.651 ; 4.7,36.901 4.7,39.651 ; 4.95,16.151 6.45,16.151 ; 4.95,16.151 6.45,16.151 ; 4.95,16.151 4.95,17.151 ; 4.95,16.151 4.95,17.151 ; 4.95,17.151 8.45,17.151 ; 4.95,17.151 8.45,17.151 ; 5.45,6.151 5.45,12.151 ; 5.45,6.151 5.45,12.151 ; 5.45,12.151 9.7,12.151 ; 5.45,12.151 9.7,12.151 ; 6.45,13.151 6.45,16.151 ; 6.45,13.151 6.45,16.151 ; 7.7,0.651 7.7,1.651 ; 7.7,0.651 7.7,1.651 ; 8.45,13.151 9.7,13.151 ; 8.45,13.151 9.7,13.151 ; 8.45,13.151 8.45,17.151 ; 8.45,13.151 8.45,17.151 ; 8.523,40.774 10.2,38.971 ; 8.523,40.774 10.2,38.971 ; 8.523,40.774 8.523,46.001 ; 8.523,40.774 8.523,46.001 ; 9.7,12.151 9.7,13.151 ; 9.7,12.151 9.7,13.151 ; 9.7,35.901 9.7,36.901 ; 9.7,35.901 9.7,36.901 ; 10.2,20.901 10.2,38.971 ; 10.2,20.901 10.2,38.971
